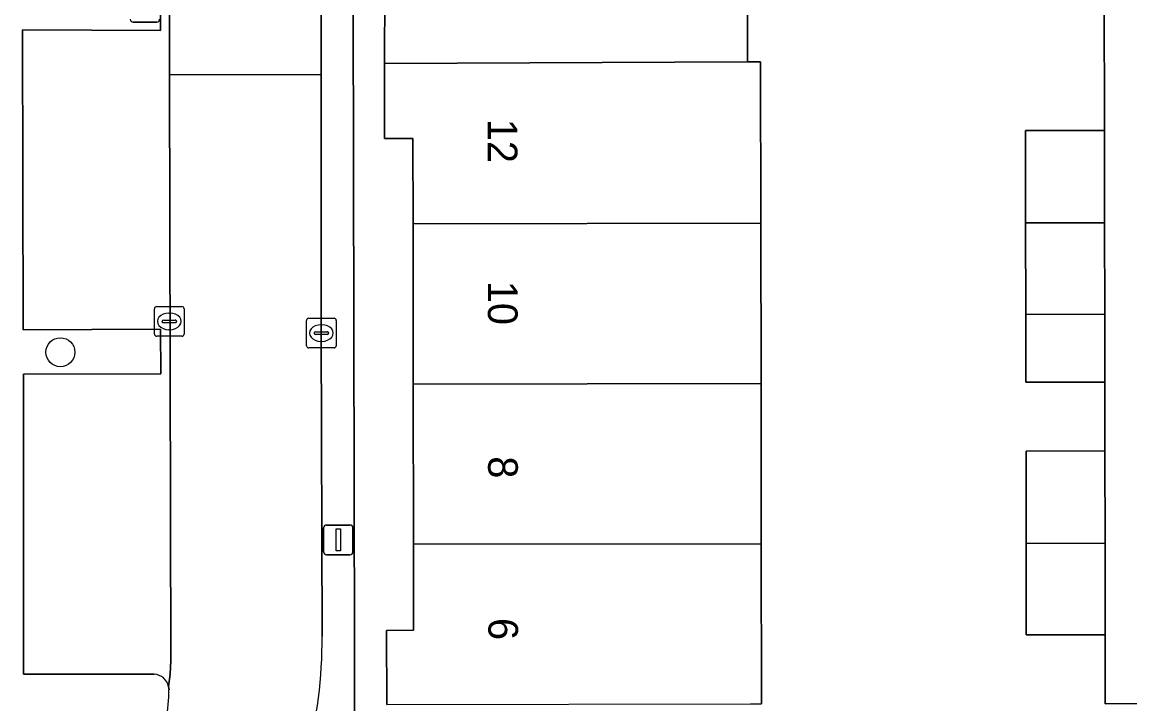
# Model space of a CAD drawing. Extents: x 160455 to 162082, y 388339 to 389736.
# Drawn here: x 160946.97 to 160984.32, y 388503.52 to 388526.51 of the extents above; entities that cross this region are included whole.
import ezdxf

# ---------------------------------------------------------------- set-up
doc = ezdxf.new("R2010")
doc.units = 0
for name, color, linetype in [('IMGEO_Boom', 7, 'Continuous'), ('IMGEO_Erf', 7, 'Continuous'), ('IMGEO_Kolk', 7, 'Continuous'), ('IMGEO_Lichtmast', 7, 'Continuous'), ('IMGEO_Pand', 7, 'Continuous'), ('IMGEO_Pand_nummerreeks', 7, 'Continuous'), ('IMGEO_Parkeervlak_open', 7, 'Continuous'), ('IMGEO_Rijbaan_lokaal_open', 7, 'Continuous'), ('IMGEO_Voetpad_open', 7, 'Continuous')]:
    doc.layers.add(name, color=color, linetype=linetype)

msp = doc.modelspace()

# ---------------------------------------------------------------- linework, layer by layer
at = {"layer": 'IMGEO_Boom'}
msp.add_circle((160948.262, 388515.379), 0.489, dxfattribs=at)
at = {"layer": 'IMGEO_Erf'}
for points in [[(160985.273, 388503.533), (160983.484, 388503.529), (160983.484, 388505.85), (160980.824, 388505.846), (160980.82, 388508.932), (160980.815, 388512.047), (160983.475, 388512.05), (160983.47, 388514.368), (160980.81, 388514.364), (160980.807, 388516.654), (160980.803, 388519.737), (160980.798, 388522.855), (160983.458, 388522.858), (160983.452, 388527.449), (160980.792, 388527.445), (160980.788, 388530.545), (160980.783, 388533.646), (160983.443, 388533.649), (160983.437, 388538.059), (160968.208, 388537.986), (160958.111, 388537.937), (160958.183, 388500)], [(160971.441, 388530.526), (160971.43, 388525.169), (160971.869, 388525.171), (160971.877, 388519.727), (160971.885, 388514.32), (160971.892, 388508.92), (160971.9, 388503.52)], [(160959.262, 388503.501), (160959.26, 388506.002), (160960.171, 388506.003), (160960.167, 388508.904), (160960.158, 388514.303), (160960.15, 388519.712), (160960.146, 388522.583), (160959.185, 388522.582), (160959.192, 388525.111), (160959.198, 388527.595)]]:
    msp.add_lwpolyline(points, dxfattribs=at)
at = {"layer": 'IMGEO_Kolk'}
for p, q in [((160951.433, 388515.992), (160951.433, 388516.844)), ((160951.508, 388516.918), (160952.36, 388516.918)), ((160951.921, 388516.698), (160951.946, 388516.698)), ((160952.434, 388516.844), (160952.434, 388515.992)), ((160951.692, 388516.412), (160951.692, 388516.424)), ((160952.13, 388516.375), (160951.732, 388516.375)), ((160951.735, 388516.461), (160952.133, 388516.461)), ((160952.176, 388516.424), (160952.176, 388516.412)), ((160956.561, 388515.598), (160956.561, 388516.45)), ((160956.636, 388516.524), (160957.488, 388516.524)), ((160957.049, 388516.304), (160957.074, 388516.304)), ((160957.562, 388516.45), (160957.562, 388515.598)), ((160952.36, 388515.918), (160951.508, 388515.918)), ((160951.944, 388516.138), (160951.919, 388516.138)), ((160956.82, 388516.018), (160956.82, 388516.03)), ((160957.258, 388515.981), (160956.86, 388515.981)), ((160956.863, 388516.067), (160957.261, 388516.067)), ((160957.304, 388516.03), (160957.304, 388516.018)), ((160957.488, 388515.524), (160956.636, 388515.524)), ((160957.072, 388515.744), (160957.047, 388515.744))]:
    msp.add_line(p, q, dxfattribs=at)
for points in [[(160951.433, 388515.992), (160951.433, 388516.844)], [(160951.508, 388516.918), (160952.36, 388516.918)], [(160952.434, 388516.844), (160952.434, 388515.992)], [(160956.561, 388515.598), (160956.561, 388516.45)], [(160956.636, 388516.524), (160957.488, 388516.524)], [(160957.562, 388516.45), (160957.562, 388515.598)], [(160952.36, 388515.918), (160951.508, 388515.918)], [(160957.488, 388515.524), (160956.636, 388515.524)]]:
    msp.add_lwpolyline(points, dxfattribs=at)
for centre, radius, start, end in [((160951.51, 388516.842), 0.0765, 91.552, 178.448), ((160951.51, 388516.842), 0.0765, 91.552, 178.448), ((160952.358, 388516.842), 0.0765, 1.552, 88.448), ((160952.358, 388516.842), 0.0765, 1.552, 88.448), ((160951.732, 388516.421), 0.0403, 85.8775, 175.7526), ((160951.729, 388516.411), 0.0366, 178.938, 274.7102), ((160952.133, 388516.418), 0.043, 264.8664, 352.4533), ((160952.137, 388516.423), 0.0386, 1.7309, 96.639), ((160956.638, 388516.448), 0.0765, 91.552, 178.448), ((160956.638, 388516.448), 0.0765, 91.552, 178.448), ((160957.486, 388516.448), 0.0765, 1.552, 88.448), ((160957.486, 388516.448), 0.0765, 1.552, 88.448), ((160951.51, 388515.994), 0.0765, 181.552, 268.448), ((160951.51, 388515.994), 0.0765, 181.552, 268.448), ((160952.358, 388515.994), 0.0765, 271.552, 358.448), ((160952.358, 388515.994), 0.0765, 271.552, 358.448), ((160956.86, 388516.027), 0.0403, 85.8775, 175.7526), ((160956.857, 388516.017), 0.0366, 178.938, 274.7102), ((160957.261, 388516.024), 0.043, 264.8664, 352.4533), ((160957.265, 388516.029), 0.0386, 1.7309, 96.639), ((160956.638, 388515.6), 0.0765, 181.552, 268.448), ((160956.638, 388515.6), 0.0765, 181.552, 268.448), ((160957.486, 388515.6), 0.0765, 271.552, 358.448), ((160957.486, 388515.6), 0.0765, 271.552, 358.448)]:
    msp.add_arc(centre, radius, start, end, dxfattribs=at)
for centre, major_axis, ratio, start_param, end_param in [((160951.92, 388516.418), (-0.387, 0.002), 0.722429, 4.712389, 7.853982), ((160951.945, 388516.418), (-0.39, 0.002), 0.717154, 1.570796, 4.712389), ((160957.048, 388516.024), (-0.387, 0.002), 0.722429, 4.712389, 7.853982), ((160957.073, 388516.024), (-0.39, 0.002), 0.717154, 1.570796, 4.712389)]:
    msp.add_ellipse(centre, major_axis=major_axis, ratio=ratio, start_param=start_param, end_param=end_param, dxfattribs=at)
at = {"layer": 'IMGEO_Lichtmast'}
for p, q in [((160951.508, 388526.506), (160950.718, 388526.506)), ((160950.718, 388526.506), (160951.508, 388526.506)), ((160957.235, 388509.553), (160958.025, 388509.553)), ((160958.025, 388509.553), (160957.235, 388509.553)), ((160957.135, 388508.653), (160957.135, 388509.453)), ((160957.135, 388509.453), (160957.135, 388508.653)), ((160958.125, 388509.453), (160958.125, 388508.653)), ((160958.125, 388508.653), (160958.125, 388509.453)), ((160958.025, 388508.553), (160957.235, 388508.553)), ((160957.235, 388508.553), (160958.025, 388508.553))]:
    msp.add_line(p, q, dxfattribs=at)
msp.add_lwpolyline([(160957.555, 388509.428), (160957.705, 388509.428), (160957.705, 388508.678), (160957.555, 388508.678), (160957.555, 388509.428)], dxfattribs=at)
for centre, start, end in [((160950.718, 388526.606), 180, 270), ((160950.718, 388526.606), 180, 270), ((160951.508, 388526.606), 270, 0), ((160951.508, 388526.606), 270, 0), ((160957.235, 388509.453), 90, 180), ((160957.235, 388509.453), 90, 180), ((160958.025, 388509.453), 0, 90), ((160958.025, 388509.453), 360, 90), ((160957.235, 388508.653), 180, 270), ((160957.235, 388508.653), 180, 270), ((160958.025, 388508.653), 270, 0), ((160958.025, 388508.653), 270, 0)]:
    msp.add_arc(centre, 0.1, start, end, dxfattribs=at)
at = {"layer": 'IMGEO_Pand'}
for points in [[(160960.135, 388530.503), (160960.139, 388527.596), (160959.198, 388527.595), (160959.192, 388525.111), (160971.43, 388525.169), (160971.441, 388530.526)], [(160960.15, 388519.712), (160971.877, 388519.727), (160971.869, 388525.171), (160971.43, 388525.169), (160959.192, 388525.111), (160959.185, 388522.582), (160960.146, 388522.583)], [(160983.463, 388519.74), (160983.458, 388522.858), (160980.798, 388522.855), (160980.803, 388519.737)], [(160971.885, 388514.32), (160971.877, 388519.727), (160960.15, 388519.712), (160960.158, 388514.303)], [(160983.463, 388519.74), (160980.803, 388519.737), (160980.807, 388516.654), (160983.467, 388516.658)], [(160983.467, 388516.658), (160980.807, 388516.654), (160980.81, 388514.364), (160983.47, 388514.368)], [(160971.885, 388514.32), (160960.158, 388514.303), (160960.167, 388508.904), (160971.892, 388508.92)], [(160980.82, 388508.932), (160983.48, 388508.936), (160983.475, 388512.05), (160980.815, 388512.047)], [(160960.167, 388508.904), (160960.171, 388506.003), (160959.26, 388506.002), (160959.262, 388503.501), (160971.53, 388503.519), (160971.9, 388503.52), (160971.892, 388508.92)], [(160980.82, 388508.932), (160980.824, 388505.846), (160983.484, 388505.85), (160983.48, 388508.936)]]:
    msp.add_lwpolyline(points, close=True, dxfattribs=at)
at = {"layer": 'IMGEO_Parkeervlak_open'}
msp.add_lwpolyline([(160951.912, 388504.108), (160951.963, 388504.524), (160951.988, 388504.991), (160951.944, 388524.736), (160951.933, 388529.556), (160951.914, 388537.902), (160946.973, 388537.864), (160946.979, 388527.753), (160951.624, 388527.737), (160951.632, 388526.228), (160946.989, 388526.245), (160947.005, 388516.136), (160951.638, 388516.161), (160951.644, 388514.648), (160947.019, 388514.641), (160947.018, 388504.529), (160951.426, 388504.522)], dxfattribs=at)
msp.add_arc((160951.398, 388503.996), 0.526, 12.2492, 86.8987, dxfattribs=at)
at = {"layer": 'IMGEO_Rijbaan_lokaal_open'}
msp.add_lwpolyline([(160951.933, 388529.556), (160951.944, 388524.736), (160957.055, 388524.739), (160957.055, 388529.559)], close=True, dxfattribs=at)
msp.add_lwpolyline([(160957.083, 388505.799), (160957.057, 388516.024), (160957.055, 388524.739), (160951.944, 388524.736), (160951.988, 388504.991), (160951.963, 388504.524), (160951.912, 388504.108), (160951.924, 388504)], dxfattribs=at)
for centre, radius, start, end in [((160942.575, 388505.615), 14.509, 344.3311, 0.7284), ((160945.139, 388504.11), 6.785, 325.5968, 359.0725)]:
    msp.add_arc(centre, radius, start, end, dxfattribs=at)
at = {"layer": 'IMGEO_Voetpad_open'}
for points in [[(160958.183, 388500), (160958.111, 388537.937), (160958.098, 388540.667), (160958.068, 388552.684), (160958.051, 388555.395), (160957.949, 388590.391), (160956.859, 388590.383), (160955.023, 388590.37), (160951.861, 388590.348), (160951.847, 388593.555), (160951.827, 388605.484), (160951.807, 388617.13)], [(160956.936, 388575.196), (160956.954, 388568.844), (160956.967, 388564.004), (160957.054, 388532.505), (160957.055, 388529.559), (160957.055, 388524.739), (160957.057, 388516.024), (160957.083, 388505.799)], [(160951.426, 388504.522), (160947.018, 388504.529), (160947.019, 388514.641), (160951.644, 388514.648), (160951.638, 388516.161), (160947.005, 388516.136), (160946.989, 388526.245), (160951.632, 388526.228), (160951.624, 388527.737), (160946.979, 388527.753), (160946.973, 388537.864), (160951.914, 388537.902), (160951.946, 388543.023)], [(160951.924, 388504), (160951.912, 388504.108)]]:
    msp.add_lwpolyline(points, dxfattribs=at)
msp.add_lwpolyline([(160985.186, 388538.067), (160983.437, 388538.059), (160983.443, 388533.649), (160983.447, 388530.55), (160983.452, 388527.449), (160983.458, 388522.858), (160983.463, 388519.74), (160983.467, 388516.658), (160983.47, 388514.368), (160983.475, 388512.05), (160983.48, 388508.936), (160983.484, 388505.85), (160983.484, 388503.529), (160985.273, 388503.533)], close=True, dxfattribs=at)
for centre, radius, start, end in [((160942.575, 388505.615), 14.509, 344.3311, 0.7284), ((160951.398, 388503.996), 0.526, 12.2492, 86.8987), ((160945.139, 388504.11), 6.785, 325.5968, 359.0725)]:
    msp.add_arc(centre, radius, start, end, dxfattribs=at)

# ---------------------------------------------------------------- texts
at = {"layer": 'IMGEO_Pand_nummerreeks'}
for s, p in [('12', (160962.666, 388523.247)), ('10', (160962.674, 388517.785)), ('8', (160962.682, 388511.869)), ('6', (160962.69, 388506.418))]:
    msp.add_text(s, height=1, rotation=270.0827, dxfattribs=at).set_placement(p)

doc.saveas('drawing.dxf')
